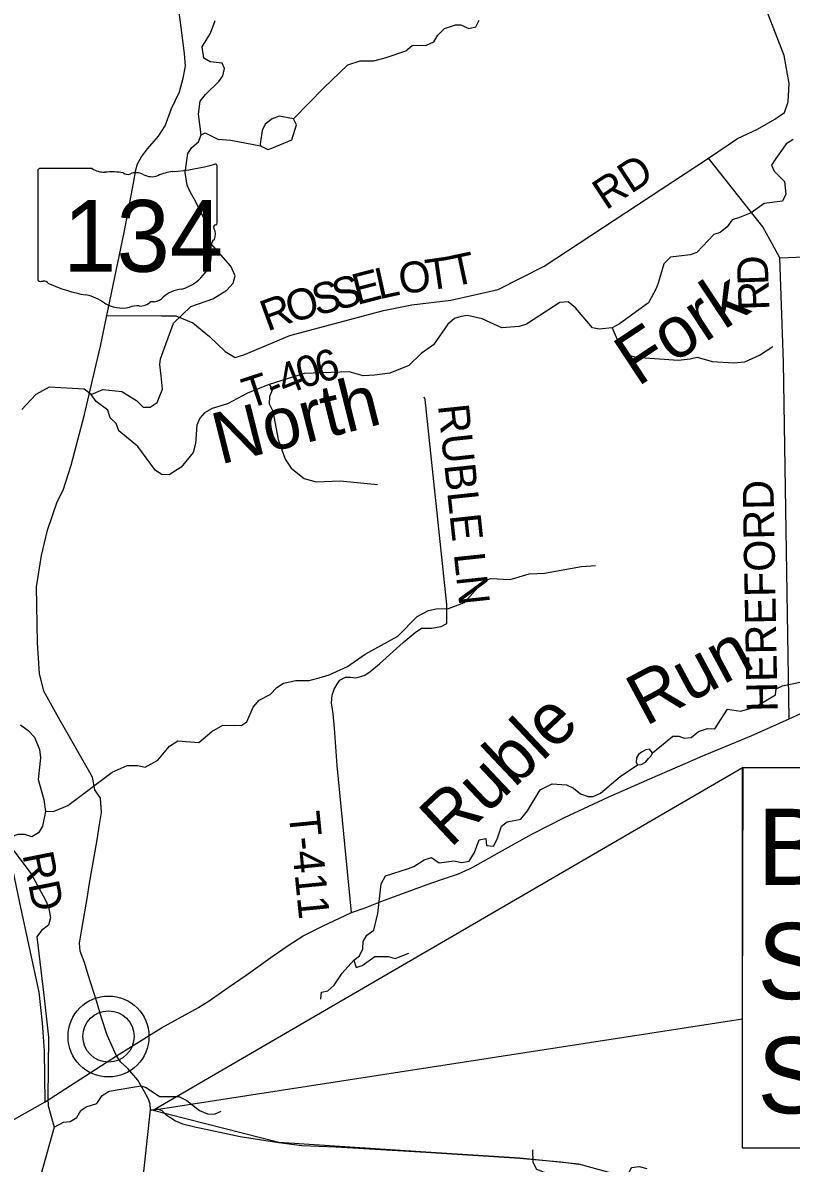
# Model space of a CAD drawing. Extents: x 0 to 34, y 0 to 22.
# Drawn here: x 3.465 to 4.877, y 18.045 to 20.142 of the extents above; entities that cross this region are included whole.
import ezdxf

# ---------------------------------------------------------------- set-up
doc = ezdxf.new("R2010")
doc.units = 0
for name, color, linetype in [('Default', 7, 'Continuous'), ('GM_X_County_Road', 7, 'Continuous'), ('GM_X_Minor_Lake', 7, 'Continuous'), ('GM_X_Minor_River', 7, 'Continuous'), ('GM_X_Minor_River_Text', 7, 'Continuous'), ('GM_X_State_Location', 7, 'Continuous'), ('GM_X_State_Route', 7, 'Continuous'), ('GM_X_State_Shield', 7, 'Continuous'), ('GM_X_Township_Road', 7, 'Continuous'), ('GM_X_Township_Road_Text', 7, 'Continuous'), ('GM_X_Unincorporated', 7, 'Continuous'), ('GM_X_Unincorporated_Location', 7, 'Continuous')]:
    doc.layers.add(name, color=color, linetype=linetype)

msp = doc.modelspace()

# ---------------------------------------------------------------- linework, layer by layer
at = {"layer": 'Default'}
for points in [[(4.7888, 18.7727), (3.7059, 18.1434), (4.7876, 18.311)], [(4.7876, 18.7727), (6.235, 18.7727), (6.235, 18.073), (4.7876, 18.073)]]:
    msp.add_lwpolyline(points, close=True, dxfattribs=at)
msp.add_lwpolyline([(8.161, 15.8436), (7.9019, 15.9854), (7.7478, 16.0791), (7.6481, 16.1403), (7.4293, 16.2693), (7.2434, 16.3742), (6.998, 16.5438), (6.6485, 16.765), (6.4043, 16.9203), (6.0579, 17.1312), (5.7891, 17.2948), (5.4666, 17.4969), (4.8712, 17.8663), (4.7185, 17.9622), (4.6135, 18.0087), (4.4868, 18.0434), (4.3784, 18.0545), (4.2056, 18.0659), (3.9354, 18.0836), (3.6991, 18.1432)], dxfattribs=at)
at = {"layer": 'GM_X_County_Road'}
msp.add_lwpolyline([(2.2799, 17.8297), (2.3457, 17.8058), (2.4145, 17.7838), (2.4313, 17.7804), (2.4446, 17.7777), (2.4762, 17.7775), (2.528, 17.7818), (2.592, 17.7876), (2.6324, 17.7878), (2.6933, 17.797), (2.8122, 17.8071), (2.9108, 17.8143), (3.0057, 17.8249), (3.0571, 17.8269), (3.0984, 17.8369), (3.1186, 17.8407), (3.1385, 17.8502), (3.1642, 17.8656), (3.218, 17.9056), (3.3195, 18.0053), (3.4349, 18.1181), (3.5055, 18.1584), (3.6368, 18.2427)], dxfattribs=at)
at = {"layer": 'GM_X_Minor_Lake'}
for points in [[(3.9225, 19.9113), (3.9592, 19.9266), (3.968, 19.9542), (3.9622, 19.9649), (3.9361, 19.9703), (3.9231, 19.9652), (3.91, 19.9555), (3.9049, 19.9439), (3.9007, 19.9185)], [(3.9007, 19.9185), (3.9014, 19.9152), (3.9151, 19.909), (3.9225, 19.9113)], [(4.5945, 18.7774), (4.6017, 18.7784), (4.6094, 18.7825), (4.6148, 18.7892), (4.6198, 18.7944), (4.6222, 18.7997), (4.617, 18.8062), (4.6098, 18.8052), (4.6021, 18.8012), (4.5964, 18.7967), (4.5932, 18.7907)], [(4.5932, 18.7907), (4.592, 18.7822), (4.5945, 18.7774)]]:
    msp.add_lwpolyline(points, dxfattribs=at)
at = {"layer": 'GM_X_Minor_River'}
for points in [[(3.59, 19.4584), (3.6114, 19.4675), (3.6466, 19.4638), (3.6737, 19.4474), (3.686, 19.4351), (3.6985, 19.4349), (3.7115, 19.4438), (3.7214, 19.4682), (3.7192, 19.4926), (3.7162, 19.5135), (3.7175, 19.5241), (3.7417, 19.5893), (3.7734, 19.6202), (3.8142, 19.6343), (3.8395, 19.6502), (3.8515, 19.6633), (3.8551, 19.6765), (3.8471, 19.6941), (3.8062, 19.7407), (3.8004, 19.7765), (3.782, 19.8136), (3.7728, 19.8297), (3.7666, 19.8434), (3.7632, 19.8666), (3.768, 19.9011), (3.7754, 19.9127), (3.7873, 19.9231), (3.7925, 19.9356), (3.7874, 19.9736), (3.7909, 19.9978), (3.8006, 20.0098), (3.8249, 20.034), (3.8323, 20.0441), (3.8356, 20.0574), (3.8312, 20.0673), (3.8092, 20.0696), (3.7972, 20.0766), (3.7945, 20.0972), (3.8097, 20.1223), (3.8185, 20.1457)], [(3.9622, 19.9649), (4.0178, 20.022), (4.0621, 20.0645), (4.085, 20.0717), (4.1097, 20.072), (4.131, 20.077), (4.1688, 20.09), (4.1807, 20.0996), (4.2069, 20.1003), (4.2202, 20.1065), (4.2277, 20.1189), (4.2396, 20.1309), (4.2599, 20.1381), (4.2701, 20.1376), (4.2844, 20.1312), (4.2973, 20.1341), (4.3036, 20.1465)], [(3.7925, 19.9356), (3.8, 19.9395), (3.8234, 19.9278), (3.8469, 19.9259), (3.9014, 19.9152)], [(4.8809, 19.9272), (4.8679, 19.919), (4.8585, 19.9052), (4.8492, 19.8924), (4.8414, 19.88), (4.8462, 19.8686), (4.8652, 19.8497), (4.8674, 19.8265), (4.8615, 19.8137), (4.8277, 19.8097), (4.8039, 19.7923), (4.7821, 19.7839), (4.7688, 19.7792), (4.7598, 19.7665), (4.7467, 19.7561), (4.7353, 19.7525), (4.704, 19.7196), (4.6914, 19.7153), (4.6553, 19.7106), (4.643, 19.6987), (4.6329, 19.6632), (4.6293, 19.6534), (4.6152, 19.6267), (4.5618, 19.5885), (4.548, 19.5812), (4.5244, 19.5782), (4.512, 19.581), (4.4807, 19.6176), (4.4673, 19.6285), (4.4521, 19.6272), (4.3907, 19.5877), (4.3774, 19.5833), (4.3455, 19.5812), (4.3093, 19.5974), (4.2821, 19.6036), (4.2707, 19.6018), (4.2581, 19.5979), (4.2462, 19.5875), (4.2197, 19.5496), (4.1971, 19.5337), (4.1743, 19.5117), (4.1392, 19.4975), (4.1114, 19.4938), (4.0902, 19.4927), (4.0645, 19.5003), (3.9821, 19.4972), (3.9177, 19.477), (3.9036, 19.4712), (3.8776, 19.461), (3.8408, 19.4412), (3.813, 19.4325), (3.7988, 19.4248), (3.7899, 19.4147), (3.7844, 19.4023), (3.7823, 19.3686), (3.7775, 19.3516), (3.7558, 19.3246), (3.7335, 19.3106), (3.7203, 19.3116), (3.7086, 19.3186), (3.676, 19.3628), (3.6409, 19.3915), (3.6362, 19.4048), (3.6253, 19.4156), (3.621, 19.4294), (3.5997, 19.4457), (3.59, 19.4584), (3.5773, 19.4681), (3.5129, 19.4718), (3.4884, 19.4582), (3.4625, 19.431)], [(4.548, 19.5812), (4.5637, 19.5452), (4.5722, 19.5326), (4.5918, 19.5269), (4.6695, 19.5214), (4.6915, 19.5241), (4.7045, 19.5273), (4.732, 19.5192), (4.7718, 19.5167), (4.792, 19.5186), (4.8191, 19.5306), (4.8436, 19.5469)], [(3.9177, 19.477), (3.9236, 19.4674), (3.9181, 19.4546), (3.9178, 19.441), (3.9244, 19.428), (3.9342, 19.3754), (3.9472, 19.3396), (3.9579, 19.3231), (3.9819, 19.3041), (4.0037, 19.2976), (4.0478, 19.2995), (4.1167, 19.2927)], [(3.5063, 18.6921), (3.5219, 18.6922), (3.5475, 18.7031), (3.629, 18.7643), (3.6565, 18.7767), (3.6758, 18.7764), (3.6898, 18.7731), (3.7128, 18.7864), (3.7341, 18.8122), (3.7494, 18.8218), (3.7881, 18.8188), (3.8119, 18.8389), (3.8326, 18.8503), (3.8534, 18.85), (3.8671, 18.8505), (3.8767, 18.8568), (3.8878, 18.8839), (3.899, 18.8966), (3.9193, 18.9069), (3.9316, 18.9199), (3.9439, 18.9277), (3.9668, 18.9326), (3.991, 18.9329), (4.0139, 18.9386), (4.0276, 18.9433), (4.0613, 18.9583), (4.0943, 18.9809), (4.154, 19.0144), (4.1895, 19.0502), (4.2106, 19.0612), (4.2247, 19.0647), (4.2474, 19.0651), (4.2768, 19.076), (4.3109, 19.1145), (4.3242, 19.1199), (4.3606, 19.1182), (4.3709, 19.1214), (4.3953, 19.1286), (4.4238, 19.13), (4.4919, 19.1425), (4.5174, 19.1443)], [(4.6222, 18.7997), (4.6457, 18.8186), (4.6599, 18.8301), (4.6709, 18.8303), (4.6807, 18.8264), (4.6932, 18.828), (4.7067, 18.8392), (4.7235, 18.8442), (4.7368, 18.8436), (4.7605, 18.88), (4.7843, 18.8762), (4.8106, 18.8837), (4.8482, 18.9066), (4.8495, 18.9175), (4.8614, 18.9226), (4.917, 18.9342)], [(3.4605, 18.851), (3.4744, 18.8409), (3.4859, 18.8282), (3.495, 18.8057), (3.497, 18.7904), (3.4926, 18.7507)], [(4.0126, 18.3471), (4.0136, 18.3596), (4.0254, 18.3625), (4.0373, 18.3725), (4.0517, 18.3946), (4.0733, 18.4189), (4.0837, 18.4263), (4.0896, 18.4394), (4.0902, 18.4527), (4.0973, 18.4647), (4.1099, 18.4736), (4.1173, 18.5042), (4.1235, 18.5587), (4.1317, 18.5737), (4.1737, 18.587), (4.1832, 18.5906), (4.2024, 18.6032), (4.2161, 18.6071), (4.23, 18.5974), (4.257, 18.6011), (4.271, 18.5979), (4.285, 18.6003), (4.2952, 18.6168), (4.3039, 18.6398), (4.3161, 18.6422), (4.317, 18.6293), (4.3299, 18.628), (4.3369, 18.6411), (4.3449, 18.6652), (4.3553, 18.6726), (4.38, 18.6775), (4.3928, 18.6929), (4.4155, 18.7315), (4.4377, 18.7429), (4.4642, 18.7406), (4.477, 18.7347), (4.4897, 18.7246), (4.504, 18.7194), (4.5135, 18.7196), (4.5265, 18.7258), (4.5627, 18.7563), (4.5945, 18.7774)], [(3.4926, 18.7507), (3.5033, 18.7141), (3.5063, 18.6921), (3.5006, 18.6652), (3.4935, 18.6528), (3.4809, 18.6451), (3.4681, 18.6495), (3.4556, 18.6497), (3.4433, 18.645), (3.4416, 18.6348), (3.4441, 18.6245), (3.4801, 18.5772), (3.5059, 18.5302), (3.5117, 18.5164), (3.5155, 18.4963), (3.5119, 18.4827), (3.4992, 18.4734), (3.4903, 18.4614), (3.5033, 18.3543), (3.5119, 18.2768), (3.5107, 18.1647), (3.5113, 18.151), (3.5224, 18.1114), (3.4978, 18.0239)], [(4.0733, 18.4189), (4.0777, 18.4052), (4.0883, 18.4088), (4.1121, 18.4254), (4.1364, 18.4254), (4.1489, 18.4218), (4.1745, 18.4316)], [(3.5224, 18.1114), (3.5396, 18.121), (3.5514, 18.1223), (3.5636, 18.1293), (3.5714, 18.142), (3.581, 18.1487), (3.6009, 18.1552), (3.6106, 18.1698), (3.6236, 18.1775), (3.6814, 18.1875), (3.6912, 18.1847), (3.7156, 18.168), (3.7513, 18.1681), (3.766, 18.1607), (3.7895, 18.1421), (3.8039, 18.1362), (3.8167, 18.1356), (3.8293, 18.141)], [(4.4018, 18.0701), (4.402, 18.0475), (4.409, 18.0345), (4.423, 18.0286), (4.4359, 18.006), (4.4596, 17.9988), (4.4817, 17.9775), (4.4922, 17.9747), (4.507, 17.9741), (4.5326, 17.9816), (4.5706, 18.0109), (4.5835, 18.0372), (4.598, 18.0392), (4.612, 18.0356)]]:
    msp.add_lwpolyline(points, dxfattribs=at)
at = {"layer": 'GM_X_State_Route'}
for points in [[(3.6056, 18.6682), (3.6091, 18.69), (3.6075, 18.7162), (3.5968, 18.7318), (3.5928, 18.7547), (3.5306, 18.8634), (3.5031, 18.9128), (3.4955, 18.9458), (3.4915, 19.0022), (3.4898, 19.1048), (3.499, 19.1623), (3.5098, 19.2091), (3.5279, 19.261), (3.5387, 19.2823), (3.5537, 19.3282), (3.5781, 19.4215), (3.5972, 19.503), (3.6075, 19.547), (3.619, 19.6034), (3.6512, 19.756), (3.6679, 19.8469), (3.6726, 19.8715), (3.6754, 19.8826), (3.6829, 19.8954), (3.6941, 19.9097), (3.7139, 19.9335), (3.7262, 19.9521), (3.7381, 19.9841), (3.7524, 20.0145), (3.7594, 20.0401), (3.7636, 20.0618), (3.762, 20.0852), (3.7441, 20.2242)], [(3.7992, 18.3391), (3.8051, 18.3428), (3.8422, 18.3684), (3.8755, 18.3913), (3.925, 18.4264), (3.9525, 18.4454), (3.9803, 18.4636), (4.0153, 18.4808), (4.0692, 18.5063), (4.0941, 18.5147), (4.1244, 18.5271), (4.1827, 18.5483), (4.2145, 18.5603), (4.2417, 18.5694), (4.2659, 18.5775), (4.2858, 18.5864), (4.2919, 18.5898), (4.341, 18.6172), (4.4003, 18.6504), (4.4608, 18.681), (4.5407, 18.7183), (4.6176, 18.7522), (4.719, 18.7961), (4.8038, 18.8309), (4.8738, 18.862), (5.0452, 18.9408)], [(3.5749, 18.4225), (3.57, 18.435), (3.5686, 18.4499), (3.5729, 18.4755), (3.5833, 18.5355), (3.5864, 18.5565), (3.6011, 18.6395), (3.6056, 18.6682)], [(3.6853, 18.0131), (3.6991, 18.1432), (3.6986, 18.1542), (3.6954, 18.163), (3.6886, 18.1765), (3.6762, 18.1979), (3.6575, 18.2194), (3.6449, 18.2312), (3.6368, 18.2427), (3.6198, 18.2805), (3.6095, 18.3127), (3.6003, 18.3437), (3.5848, 18.3917), (3.5781, 18.4144), (3.5749, 18.4225)], [(3.6368, 18.2427), (3.7195, 18.294), (3.7873, 18.3315), (3.7992, 18.3391)], [(3.6991, 18.1432), (3.7059, 18.1434), (3.712, 18.1451), (3.7199, 18.1422), (3.7277, 18.1352), (3.7366, 18.1285), (3.7452, 18.1233), (3.758, 18.1177), (3.7806, 18.1121), (3.864, 18.0943), (3.9354, 18.0836), (3.9774, 18.0779), (4.0403, 18.0754), (4.2056, 18.0659), (4.3784, 18.0545), (4.4538, 18.0482), (4.4868, 18.0434)]]:
    msp.add_lwpolyline(points, dxfattribs=at)
at = {"layer": 'GM_X_State_Shield'}
for p, q in [((3.592, 19.8735), (3.4955, 19.8735)), ((3.8218, 19.7737), (3.8218, 19.8784)), ((3.4922, 19.87), (3.4922, 19.6699)), ((3.8218, 19.7738), (3.8218, 19.7737))]:
    msp.add_line(p, q, dxfattribs=at)
for centre, major_axis, start_param, end_param in [((3.496, 19.8704), (0.00382, 0), 1.712693, 3.28349), ((3.615, 19.8967), (0.037, 0), 4.042523, 4.731795), ((3.7044, 20.1463), (0.3495, 0), 4.814394, 5.042369), ((3.8181, 19.8789), (0.00367, 0), 6.141152, 7.989035), ((3.6272, 19.7611), (0.133, 0), 1.404758, 1.657858), ((3.6574, 19.8715), (0.0107, 0), 3.836095, 5.185415), ((3.6731, 19.8484), (0.0222, 0), 0.950623, 2.079405), ((3.7018, 19.8801), (0.0267, 0), 4.081561, 5.145723), ((3.749, 19.8123), (0.0703, 0), 1.699011, 2.107814), ((3.8209, 19.7661), (0.00568, 0), 1.883978, 3.671073), ((3.8179, 19.7733), (0.00393, 0), 5.05454, 6.418171), ((3.7848, 19.7528), (0.0341, 0), 5.934695, 6.695948), ((3.724, 19.7166), (0.0874, 0), 5.101752, 6.440018), ((3.8349, 19.7299), (0.0248, 0), 2.387724, 3.262537), ((3.496, 19.6695), (0.00385, 0), 3.00124, 4.508301), ((3.4966, 19.6899), (0.0294, 0), 4.665946, 4.897461), ((3.5026, 19.6584), (0.0106, 0), 0.519207, 1.627899), ((3.6364, 19.8382), (0.2524, 0), 4.195997, 4.488961), ((3.7608, 19.6137), (0.0479, 0), 1.647645, 2.488434), ((3.5612, 19.58), (0.079, 0), 0.823519, 1.323587), ((3.6466, 19.6574), (0.0501, 0), 4.026481, 4.996735), ((3.6756, 19.5882), (0.0412, 0), 1.495662, 1.94098), ((3.6792, 19.6424), (0.0267, 0), 4.691044, 5.507374), ((3.7034, 19.623), (0.00752, 0), 1.147584, 2.315152), ((3.7002, 19.6505), (0.0282, 0), 4.937069, 5.64225)]:
    msp.add_ellipse(centre, major_axis=major_axis, ratio=0.8, start_param=start_param, end_param=end_param, dxfattribs=at)
at = {"layer": 'GM_X_Township_Road'}
for points in [[(4.8738, 18.862), (4.8629, 19.5178), (4.8567, 19.7096), (4.825, 19.7664), (4.725, 19.8931), (4.7788, 19.9289), (4.8156, 19.9458), (4.8475, 19.9642), (4.8648, 19.9768), (4.8716, 19.9964), (4.8737, 20.0298), (4.8643, 20.0816), (4.7796, 20.2995), (4.7681, 20.3149), (4.7293, 20.3148), (4.3645, 20.2742), (3.973, 20.2502), (3.9306, 20.2384), (3.8852, 20.2282), (3.8365, 20.2207), (3.789, 20.22), (3.7441, 20.2242)], [(4.8567, 19.7096), (5.0517, 19.7173), (5.1331, 19.7208), (5.154, 19.7227), (5.1685, 19.7243), (5.1792, 19.731), (5.1811, 19.7507), (5.1785, 19.8666), (5.1803, 19.8783), (5.1857, 19.8862), (5.1946, 19.8944), (5.2141, 19.9009), (5.2366, 19.9077), (5.263, 19.9205), (5.2979, 19.9374), (5.327, 19.9475), (5.4943, 19.9803), (5.731, 20.0244)], [(3.619, 19.6034), (3.7194, 19.603), (3.7459, 19.6029), (3.7773, 19.5903), (3.808, 19.5647), (3.8367, 19.5372), (3.8548, 19.5266), (3.8712, 19.5313), (3.9554, 19.5666), (4.1279, 19.613), (4.1798, 19.6235), (4.2513, 19.6317), (4.3387, 19.6515), (4.423, 19.6944), (4.725, 19.8931)], [(4.0692, 18.5063), (4.0428, 18.7762), (4.0379, 18.845), (4.0349, 18.8712), (4.0319, 18.8918), (4.0332, 18.9054), (4.0372, 18.9168), (4.0423, 18.9258), (4.0474, 18.9333), (4.0577, 18.9388), (4.0669, 18.939), (4.0771, 18.9377), (4.0924, 18.9416), (4.1024, 18.9487), (4.1205, 18.9631), (4.1637, 19.0026), (4.1857, 19.0212), (4.1976, 19.0286), (4.2158, 19.0291), (4.2337, 19.0318), (4.2444, 19.0373), (4.2443, 19.0726), (4.2043, 19.4493), (4.2026, 19.4534)], [(3.5055, 18.1584), (3.5044, 18.2522), (3.5005, 18.3031), (3.4946, 18.3597), (3.4589, 18.5238), (3.4338, 18.6449)]]:
    msp.add_lwpolyline(points, dxfattribs=at)
at = {"layer": 'GM_X_Unincorporated'}
for radius in [0.0744, 0.0472]:
    msp.add_circle((3.6221, 18.2783), radius, dxfattribs=at)
at = {"layer": 'GM_X_Unincorporated_Location'}
msp.add_line((3.6221, 18.2783), (3.6221, 18.2783), dxfattribs=at)

# ---------------------------------------------------------------- texts
at = {"layer": 'Default'}
for s, p in [('BEGIN PROJECT', (4.8152, 18.557)), ('S.R. 321', (4.8152, 18.347)), ('S.L.M. 0.000', (4.8152, 18.137))]:
    msp.add_text(s, height=0.14, dxfattribs=at).set_placement(p)
at = {"layer": 'GM_X_Minor_River_Text'}
for s, height, rotation, p in [('Fork', 0.0947, 33.4435, (4.5949, 19.4716)), ('North', 0.0947, 14.1369, (3.8274, 19.3293)), ('Run', 0.09469, 28.2454, (4.6094, 18.8478)), ('Ruble', 0.09467, 43.3916, (4.2506, 18.6231))]:
    msp.add_text(s, height=height, rotation=rotation, dxfattribs=at).set_placement(p)
at = {"layer": 'GM_X_State_Location'}
for s in ['s', 'r']:
    msp.add_text(s, height=0.000189, dxfattribs=at).set_placement((3.6533, 19.7567))
msp.add_text('134', height=0.000189, rotation=0, dxfattribs=at).set_placement((3.5864, 19.7429))
at = {"layer": 'GM_X_State_Shield'}
msp.add_text('134', height=0.13184, dxfattribs=at).set_placement((3.5387, 19.684))
at = {"layer": 'GM_X_Township_Road_Text'}
for s, height, rotation, p in [('RD', 0.05682, 33.2748, (4.5367, 19.7963)), ('O', 0.0568, 8.3644, (4.1598, 19.6421)), ('T', 0.0568, 8.1616, (4.2093, 19.6494)), ('T', 0.0568, 12.1377, (4.2556, 19.6562)), ('D', 0.0568, 91.9383, (4.8358, 19.6601)), ('E', 0.0568, 14.4673, (4.0788, 19.6226)), ('L', 0.0568, 12.4884, (4.1194, 19.6331)), ('S', 0.0568, 14.8818, (4.0048, 19.603)), ('S', 0.0568, 14.872, (4.0418, 19.6128)), ('R', 0.0568, 92.0105, (4.8374, 19.6135)), ('O', 0.0568, 15.6654, (3.9568, 19.5895)), ('R', 0.0568, 20.0048, (3.9141, 19.5739)), ('6', 0.0568, 15.207, (4.0105, 19.479)), ('4', 0.0568, 22.1382, (3.9464, 19.4557)), ('0', 0.0568, 17.7689, (3.9778, 19.4685)), ('T', 0.0568, 18.1649, (3.8797, 19.4314)), ('-', 0.0568, 23.2381, (3.9252, 19.4466)), ('RUBLE LN', 0.05682, 276.0904, (4.2278, 19.4383)), ('HEREFORD', 0.05682, 91.0416, (4.8524, 18.8755)), ('T-411', 0.05682, 275.6269, (3.9533, 18.6896)), ('RD', 0.05682, 281.3013, (3.4635, 18.6125))]:
    msp.add_text(s, height=height, rotation=rotation, dxfattribs=at).set_placement(p)

doc.saveas('drawing.dxf')
